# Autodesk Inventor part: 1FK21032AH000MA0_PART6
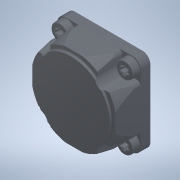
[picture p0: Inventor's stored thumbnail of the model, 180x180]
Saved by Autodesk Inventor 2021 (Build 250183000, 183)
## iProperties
Created: 2025-04
Part Number: 1FK21032AH000MA0_PART6
Material: Generic
Catalog Web Link: www.3dfindit.com
Description: -Servo synchronous motor
Document SubType Name: Modeling
Designer: psAdmin
Mass: 3.85693 g
Surface Area: 17.8404 cm^2
Volume: 3.85693 cm^3
Density: 1 g/cm^3
Appearance: PSOLRGB-48-56-69
Category: PARTsolutions
Title: 1FK21032AH000MA0_PART6
Author: Cadenas PARTsolutions
Comments: Servo synchronous motor
Sending System: PARTsolutions
Preprocessor: ST-DEVELOPER v19.3
PSOL_IDENT_0: {$CADENAS_DATA/23d-libs/siemens_ag/_cat_/45/10/1fk21032ah000ma0.prj},213 {VTYP=3D},{NB=1FK21032AH000
PSOL_IDENT_1: MA0_PART6},{LINA=1FK21032AH000MA0_PART6},{NN=1FK21032AH000MA0_PART6},{NOPRJ=TRUE},{DATE=19.08.2025 1
PSOL_IDENT_2: 4:00:35},{GEOMDATE=30.07.2025 02:02:03},{VERSION=},{LINEID=10},{WBVAR=},{WBNUMERIC=}  {NB=1FK21032AH
PSOL_IDENT_3: 000MA0_PART6},{LINA=1FK21032AH000MA0_PART6},{KT=DUMMY},{PREVIEW=../../../_pool_/14/8e/p_d211_xx_0042
PSOL_IDENT_4: 6j.png},{DESCSHORT=SIMOTICS S-1FK2 HD, SINAMICS S210 3AC 400V-480V, 0.59 Nm, 4500 rpm},{DESCLONG=SIM
PSOL_IDENT_5: OTICS S-1FK2 HD servo motor M0=0.64 Nm; PN = 0.28 kW at nN=4500 rpm (380-480 V); PN = 0.167 kW at nN=
PSOL_IDENT_6: 2500 rpm (200-240 V); degree of protection IP64; cylindrical shaft D14 x 30 mm; absolute encoder 22-
PSOL_IDENT_7: bit + 12-bit multiturn (encoder AM22DQC); with OCC interface; plug size M17, rotatable; SIMOTICS S-1
PSOL_IDENT_8: FK2 servomotorfor a wide range of uses in industrial environments. SIMOTICS S‑1FK2 servomotors are c
PSOL_IDENT_9: ompact synchronous motors with a high dynamic performance that set themselves apart as a result of t
PSOL_IDENT_10: heir high power density, degree of protection and overload capability. The motors are available in t
PSOL_IDENT_11: wo variants: as High Dynamic variant (highest dynamic performance as a result of the low intrinsic m
PSOL_IDENT_12: oment of inertia for applications demanding a high dynamic performance with low moved masses) - and
PSOL_IDENT_13: as Compact variant (precise and stable closed-loop control for medium up to large moved masses as a
PSOL_IDENT_14: result of a medium intrinsic moment of inertia). SIMOTICSS‑1FK2 servomotors fully exploit their stre
PSOL_IDENT_15: ngths in a system with the SINAMICSS210 frequency converter and simple connection using the one cabl
PSOL_IDENT_16: e connection (OCC). Advantages include the short control and positioning times, fast and precise cor
PSOL_IDENT_17: rection of disturbing quantities as well as stable control with a high dynamic performance. The serv
PSOL_IDENT_18: o motors can be configured to address a wide range of requirements. For example with and without hol
PSOL_IDENT_19: ding brake, IP64 or IP65 degree of protection, singleturn or multiturn absolute encoders - to name j
PSOL_IDENT_20: ust a few. Further, the servomotors are available in different shaft heights extending from 20 to 10
PSOL_IDENT_21: 0. A shaft sealing ring is available to achieve an IP65 degree of protection and for subsequent moun
PSOL_IDENT_22: ting at the motor or as spare part. SIMOTICS - the optimum motor for each and every motion control a
PSOL_IDENT_23: pplication.},{INTNO=195125335004},{SUPPLIERALTNO=1FK2103-2AH00-0MA0},{MANUID=1FK21032AH000MA0},{MANU
PSOL_IDENT_24: NAME=Siemens},{MANUTYPEDESC=SYNCHRONOUS MOTOR 1FK2 HD 0,64 NM},{AAU732=SIMOTICS},{AAO057=S-1FK2},{AA
PSOL_IDENT_25: U734=SIMOTICS S-1FK2 HD servo motor M0=0.64 Nm; PN = 0.28 kW at nN=4500 rpm (380-480 V); PN = 0.167
PSOL_IDENT_26: kW at nN=2500 rpm (200-240 V); degree of protection IP64; cylindrical shaft D14 x 30 mm; absolute en
PSOL_IDENT_27: coder 22-bit + 12-bit multiturn (encoder AM22DQC); with OCC interface; plug size M17, rotatable;},{A
PSOL_IDENT_28: AW338=SYNCHRONOUS MOTOR 1FK2 HD 0,64 NM},{AAO742=SIMOTICS},{AAO663=4034106444624},{NOCUPEROU=1},{PRI
PSOL_IDENT_29: CEQUANTITY=1},{QUANTITYMIN=1},{QUANTITYINT=1},{CTN=85015100},{COO=RO},{AAO676=1FK2103-2AH00-0MA0},{A
PSOL_IDENT_30: AO677=Siemens AG},{ORDERUNIT=C62},{CONTENTUNIT=C62}
NB: 1FK21032AH000MA0_PART6
NT: Servo synchronous motor
NBSYN: $MANUID._PART6
LINA: 1FK21032AH000MA0_PART6
CATALOG: SIEMENS
PREVIEW: ../../../_pool_/14/8e/p_d211_xx_00426j.png
DESCSHORT: SIMOTICS S-1FK2 HD, SINAMICS S210 3AC 400V-480V, 0.59 Nm, 4500 rpm
DESCLONG: SIMOTICS S-1FK2 HD servo motor M0=0.64 Nm; PN = 0.28 kW at nN=4500 rpm (380-480 V); PN = 0.167 kW at nN=2500 rpm (200-240 V); degree of protection IP64; cylindr
INTNO: 195125335004
SUPPLIERALTNO: 1FK2103-2AH00-0MA0
MANUID: 1FK21032AH000MA0
MANUNAME: Siemens
MANUTYPEDESC: SYNCHRONOUS MOTOR 1FK2 HD 0,64 NM
AAU732: SIMOTICS
AAO057: S-1FK2
AAU734: SIMOTICS S-1FK2 HD servo motor M0=0.64 Nm; PN = 0.28 kW at nN=4500 rpm (380-480 V); PN = 0.167 kW at nN=2500 rpm (200-240 V); degree of protection IP64; cylindr
AAW338: SYNCHRONOUS MOTOR 1FK2 HD 0,64 NM
AAO742: SIMOTICS
AAO663: 4034106444624.0
NOCUPEROU: 1
PRICEQUANTITY: 1
QUANTITYMIN: 1
QUANTITYINT: 1
CTN: 85015100
COO: RO
ARTICLENO: 1FK21032AH000MA0_PART6
BOMINFO: 1FK21032AH000MA0_PART6
CREATOR: CADENAS GmbH
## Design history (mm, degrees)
feature "2025_04_17_15_00_20_0697"
body "Solid1"
